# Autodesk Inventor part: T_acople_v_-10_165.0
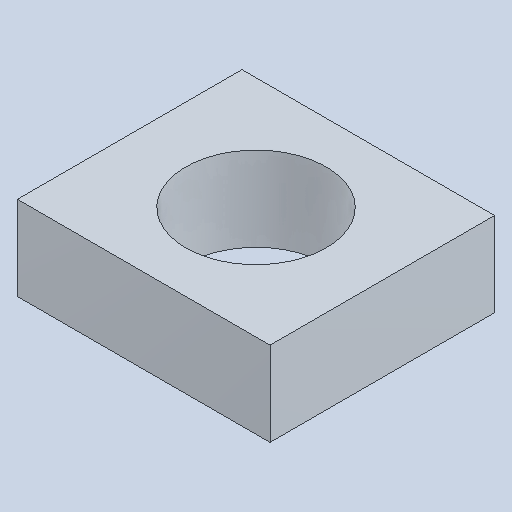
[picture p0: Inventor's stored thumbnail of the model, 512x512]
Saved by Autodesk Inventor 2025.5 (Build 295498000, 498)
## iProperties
Created: 2026-10
Part Number: T_acople_v_-10_165.0
Material: Genérico
Document SubType Name: Modeling
Designer: Luis M
Density: 1 g/cm^3
Appearance: Valor por defecto
Author: Luis M
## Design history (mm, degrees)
feature "Base1"
node "Sólido1"
